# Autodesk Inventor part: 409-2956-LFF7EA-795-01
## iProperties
Created: 2010-09
Part Number: 409-2956-LFF7EA-795-01
Material: 3/4" LIQUID TIGHT
Document SubType Name: Modeling
Designer: S. Boerckel
Engineer: Steve Boerckel
Mass: 232.246 g
Surface Area: 912.875 cm^2
Volume: 165.89 cm^3
Density: 1.4 g/cm^3
Description: LIQUID TIGHT
Length: 13.776 in
Author: S. Boerckel
Revision Number: 0
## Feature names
1. Sweep1
